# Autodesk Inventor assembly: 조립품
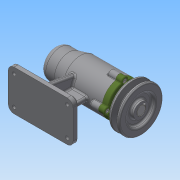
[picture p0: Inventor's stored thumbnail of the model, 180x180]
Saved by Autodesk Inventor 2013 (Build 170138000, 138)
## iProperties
Created: 2019-07
Part Number: 조립품
Document SubType Name: Assembly
Designer: Administrator
Author: Administrator
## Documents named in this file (12)
- C:\Users\Administrator\Desktop\490704V1024\조립품.iam
- C:\Users\Administrator\Desktop\490704V1024\본체.ipt
- C:\Users\Administrator\Desktop\490704V1024\V벨트풀리.ipt
- C:\Users\Administrator\Desktop\490704V1024\멈춤나사 M3.ipt
- C:\Users\Administrator\Desktop\490704V1024\베어링 6004.ipt
- C:\Users\Administrator\Desktop\490704V1024\베어링 51202.ipt
- C:\Users\Administrator\Desktop\490704V1024\볼트 M4.ipt
- C:\Users\Administrator\Desktop\490704V1024\어댑터슬리브.ipt
- C:\Users\Administrator\Desktop\490704V1024\오일 실.ipt
- C:\Users\Administrator\Desktop\490704V1024\축.ipt
- C:\Users\Administrator\Desktop\490704V1024\커버.ipt
- C:\Users\Administrator\Desktop\490704V1024\키 5 x 5 x 16.ipt
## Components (1 placed, 1 different names)
1. V벨트풀리:1
